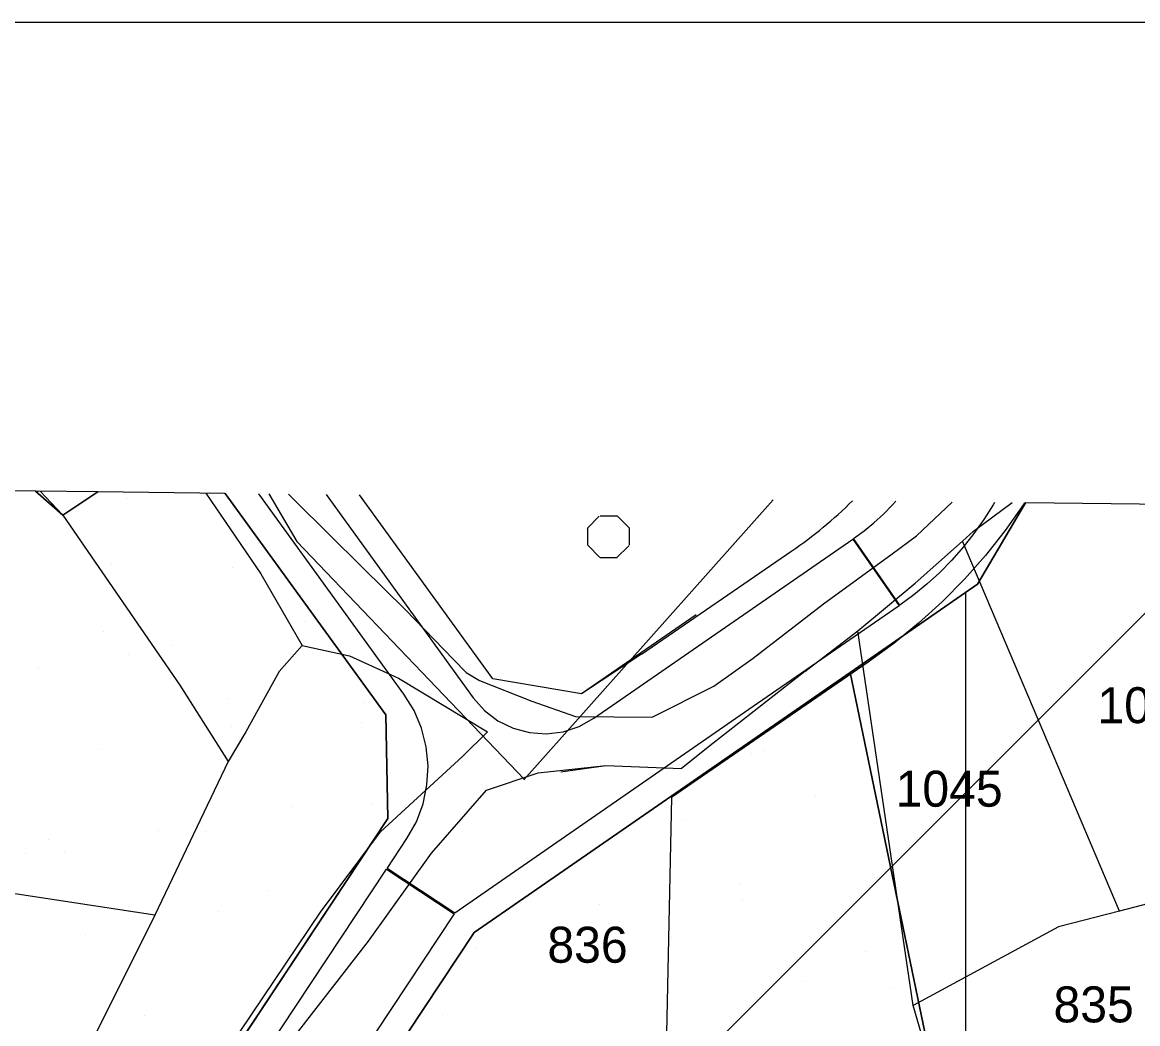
# Model space of a CAD drawing. Extents: x 410727 to 412947, y 4463506 to 4466382.
# Drawn here: x 410944.2 to 411068.2, y 4466270.3 to 4466381.6 of the extents above; entities that cross this region are included whole.
import ezdxf

# ---------------------------------------------------------------- set-up
doc = ezdxf.new("R2010")
doc.units = 0
for name, color, linetype in [('ADAKENARI', 7, 'Continuous'), ('F_ADAKENARI', 7, 'Continuous'), ('KALDIRIM', 7, 'Continuous'), ('KDS_PARSEL_NO', 7, 'Continuous'), ('KDS_PL', 7, 'Continuous'), ('LJ_ÇERÇEVE', 7, 'Continuous'), ('PL_AYA_PARK_DINLENME', 7, 'Continuous'), ('PL_KON_MEV_050', 7, 'Continuous'), ('SNR_KOYLER', 7, 'Continuous'), ('SNR_TR_AZGELISME', 7, 'Continuous'), ('TR_AZYOGUNLUK_MESKUN', 7, 'Continuous'), ('TR_OZELMAHSUL', 7, 'Continuous'), ('TR_PARKALANI', 7, 'Continuous'), ('Yerlesime_uygunluk_sınırı', 7, 'Continuous')]:
    doc.layers.add(name, color=color, linetype=linetype)

msp = doc.modelspace()

# ---------------------------------------------------------------- linework, layer by layer
at = {"layer": 'ADAKENARI'}
for p, q in [((410948.75, 4466326.83), (410945.69, 4466329.49)), ((410952.62, 4466329.41), (410948.75, 4466326.83)), ((410966.77, 4466329.24), (410984.62, 4466304.63)), ((411013.07, 4466311.39), (411029.75, 4466322.85)), ((411013.07, 4466311.39), (411029.75, 4466322.85)), ((411019.12, 4466315.76), (411006.4, 4466306.96)), ((411013.07, 4466311.39), (411006.4, 4466306.96)), ((411006.4, 4466306.96), (410996.54, 4466308.64)), ((410984.62, 4466304.63), (410984.87, 4466293.13)), ((410984.87, 4466293.13), (410937.01, 4466220.86))]:
    msp.add_line(p, q, dxfattribs=at)
for points in [[(411192.1, 4466326.6), (411199.04, 4466311.27), (411191.3, 4466278.41), (411195.67, 4466251.72), (411191.89, 4466226.13), (411190.31, 4466188.93), (411154.6, 4466192.84), (411154.89, 4466194.74), (411133.79, 4466195.19), (411131.16, 4466218.16), (411125.23, 4466237.12), (411061.36, 4466220.11), (411049.97, 4466245.63), (411049.01, 4466247.79), (411036.24, 4466309.36), (411050.41, 4466319.17), (411055.74, 4466328.2)], [(410994.47, 4466280.46), (411036.24, 4466309.36), (411049.01, 4466247.79), (411049.97, 4466245.63), (410970.35, 4466244.04), (410994.47, 4466280.46)]]:
    msp.add_lwpolyline(points, dxfattribs=at)
msp.add_arc((411001.42, 4466364.05), 50, 304.5085, 314.5543, dxfattribs=at)
msp.add_arc((411001.42, 4466364.05), 50, 304.5085, 314.5543, dxfattribs=at)
msp.add_arc((411001.42, 4466364.05), 50, 304.5085, 314.5543, dxfattribs=at)
at = {"layer": 'F_ADAKENARI'}
for p, q in [((410996.54, 4466308.64), (410981.72, 4466329.07)), ((411006.4, 4466306.96), (410996.54, 4466308.64))]:
    msp.add_line(p, q, dxfattribs=at)
at = {"layer": 'KALDIRIM'}
for points in [[(410977.99, 4466329.11), (410994.36, 4466306.54), (410995.6, 4466305.13), (410997.1, 4466303.99), (410998.78, 4466303.16), (411000.6, 4466302.66), (411002.47, 4466302.53), (411004.34, 4466302.76), (411006.12, 4466303.34), (411007.77, 4466304.25), (411020.83, 4466313.29), (411036.54, 4466324.17), (411041.67, 4466316.77), (411025.95, 4466305.89), (410992.29, 4466282.6), (410984.79, 4466287.57), (410986.99, 4466290.89), (410988.03, 4466292.76), (410988.78, 4466294.76), (410989.21, 4466296.85), (410989.33, 4466298.98), (410989.12, 4466301.1), (410988.6, 4466303.17), (410987.77, 4466305.13), (410986.65, 4466306.95), (410970.51, 4466329.2)], [(411052.28, 4466328.24), (411052.12, 4466327.98), (411052.12, 4466327.98), (411051.1, 4466326.35), (411050, 4466324.78), (411048.81, 4466323.28), (411047.54, 4466321.84), (411046.2, 4466320.47), (411044.78, 4466319.17), (411043.3, 4466317.96), (411041.75, 4466316.83), (411041.75, 4466316.83), (411036.63, 4466324.23), (411037.78, 4466325.07), (411038.89, 4466325.98), (411039.95, 4466326.95), (411040.95, 4466327.97), (411041.3, 4466328.37)], [(410877.26, 4466132.92), (410902.91, 4466163.94), (410984.73, 4466287.49), (410992.24, 4466282.52), (410910.15, 4466158.57), (410883.93, 4466126.86)]]:
    msp.add_lwpolyline(points, dxfattribs=at)
at = {"layer": 'KDS_PL'}
for p, q in [((410946.22, 4466329.48), (410948.75, 4466326.83)), ((410964.62, 4466329.27), (410970.75, 4466320.32)), ((410973.82, 4466329.16), (410974.53, 4466328.47)), ((410974.53, 4466328.47), (410982.05, 4466321)), ((411043.6, 4466324.53), (411047.58, 4466328.29)), ((411049.96, 4466325.05), (411054.26, 4466328.22)), ((410948.75, 4466326.83), (410961.76, 4466307.95)), ((411048.71, 4466323.94), (411049.96, 4466325.05)), ((411040.91, 4466322.53), (411043.6, 4466324.53)), ((411043.48, 4466319.28), (411048.71, 4466323.94)), ((411066.16, 4466282.83), (411048.71, 4466323.94)), ((411033.26, 4466316.96), (411040.91, 4466322.53)), ((410970.75, 4466320.32), (410975.33, 4466312.34)), ((410982.05, 4466321), (410986.83, 4466316.31)), ((411037.09, 4466313.99), (411043.48, 4466319.28)), ((410986.83, 4466316.31), (410992.16, 4466310.79)), ((411025.46, 4466310.93), (411033.26, 4466316.96)), ((411031.21, 4466309.44), (411037.09, 4466313.99)), ((411043.25, 4466272.34), (411037.09, 4466313.99)), ((410975.33, 4466312.34), (410972.78, 4466309.45)), ((410975.33, 4466312.34), (410980.6, 4466311.18)), ((410980.6, 4466311.18), (410986.04, 4466308.71)), ((410992.16, 4466310.79), (410993.55, 4466309.36)), ((411021.1, 4466307.83), (411025.46, 4466310.93)), ((410972.78, 4466309.45), (410969.07, 4466302.75)), ((410986.04, 4466308.71), (410995.93, 4466302.76)), ((410993.55, 4466309.36), (410995.04, 4466308.47)), ((411031.21, 4466309.44), (411020.98, 4466301.46)), ((410961.76, 4466307.95), (410967.11, 4466299.44)), ((410995.04, 4466308.47), (411000.88, 4466306.16)), ((411014.24, 4466304.39), (411021.1, 4466307.83)), ((411000.88, 4466306.16), (411005.7, 4466304.44)), ((411005.7, 4466304.44), (411014.24, 4466304.39)), ((410969.07, 4466302.75), (410967.11, 4466299.44)), ((410993.21, 4466300.04), (410995.93, 4466302.76)), ((411020.98, 4466301.46), (411017.49, 4466298.68)), ((410984.06, 4466291.62), (410993.21, 4466300.04)), ((410967.11, 4466299.44), (410958.96, 4466282.37)), ((411001.57, 4466298.18), (411009.07, 4466299)), ((411004.08, 4466298.31), (411009.07, 4466299)), ((411009.07, 4466299), (411017.49, 4466298.68)), ((410995.84, 4466296.27), (411001.57, 4466298.18)), ((410989.7, 4466289.26), (410995.84, 4466296.27)), ((410958.96, 4466282.37), (410894.78, 4466292.22)), ((410977.39, 4466282.71), (410984.06, 4466291.62)), ((410982.7, 4466279.49), (410989.7, 4466289.26)), ((411085.99, 4466287.93), (411066.16, 4466282.83)), ((410966.52, 4466266.61), (410977.39, 4466282.71)), ((411066.16, 4466282.83), (411059.38, 4466281.08)), ((410958.96, 4466282.37), (410947.29, 4466258.94)), ((411059.38, 4466281.08), (411043.25, 4466272.34)), ((410971.47, 4466265.05), (410982.7, 4466279.49)), ((411045.67, 4466264.11), (411043.25, 4466272.34))]:
    msp.add_line(p, q, dxfattribs=at)
at = {"layer": 'LJ_ÇERÇEVE'}
msp.add_lwpolyline([(410732.32, 4466381.6), (412946.74, 4466381.6), (412946.74, 4463506.16), (410732.32, 4463506.16)], close=True, dxfattribs=at)
at = {"layer": 'PL_AYA_PARK_DINLENME'}
for points in [[(410966.77, 4466329.24), (410952.62, 4466329.41), (410948.75, 4466326.83), (410945.69, 4466329.49), (410864.92, 4466330.44), (410865.03, 4466330.16), (410905.8, 4466318.77), (410931.26, 4466291.1), (410937.01, 4466220.86), (410984.87, 4466293.13), (410984.62, 4466304.63), (410966.77, 4466329.24)], [(410994.47, 4466280.46), (410970.35, 4466244.04), (411049.97, 4466245.63), (411049.01, 4466247.79), (411036.24, 4466309.36), (410994.47, 4466280.46)]]:
    msp.add_lwpolyline(points, dxfattribs=at)
at = {"layer": 'PL_KON_MEV_050'}
for points in [[(410952.62, 4466329.41), (410945.69, 4466329.49), (410948.75, 4466326.83), (410952.62, 4466329.41)], [(411192.1, 4466326.6), (411055.74, 4466328.2), (411050.41, 4466319.17), (411036.24, 4466309.36), (411049.01, 4466247.79), (411049.97, 4466245.63), (411058.74, 4466226), (411061.36, 4466220.11), (411125.23, 4466237.12), (411131.16, 4466218.16), (411133.79, 4466195.19), (411154.89, 4466194.74), (411154.6, 4466192.84), (411190.31, 4466188.93), (411191.89, 4466226.13), (411195.67, 4466251.72), (411191.3, 4466278.41), (411199.04, 4466311.27), (411192.1, 4466326.6)]]:
    msp.add_lwpolyline(points, dxfattribs=at)
at = {"layer": 'SNR_KOYLER'}
for p, q in [((411055.52, 4466328.03), (411053.48, 4466325.14)), ((411055.63, 4466328.2), (411055.52, 4466328.03)), ((411053.48, 4466325.14), (411051.29, 4466322.36)), ((411051.29, 4466322.36), (411048.95, 4466319.71)), ((411048.95, 4466319.71), (411046.46, 4466317.19)), ((411046.46, 4466317.19), (411043.85, 4466314.81)), ((411043.85, 4466314.81), (411041.1, 4466312.57)), ((411041.1, 4466312.57), (411038.24, 4466310.49)), ((411038.24, 4466310.49), (411016.4, 4466295.47)), ((411016.4, 4466295.47), (411011.82, 4466089.82))]:
    msp.add_line(p, q, dxfattribs=at)
at = {"layer": 'SNR_TR_AZGELISME'}
msp.add_line((411015.66, 4466262.59), (411080.98, 4466327.9), dxfattribs=at)
at = {"layer": 'TR_AZYOGUNLUK_MESKUN'}
for p, q in [((410945.91, 4466329.3), (410945.91, 4466329.49)), ((411049.1, 4466247.57), (411049.1, 4466318.27))]:
    msp.add_line(p, q, dxfattribs=at)
msp.add_lwpolyline([(411055.74, 4466328.2), (411050.41, 4466319.17), (411036.24, 4466309.36), (411049.01, 4466247.79), (411049.97, 4466245.63), (411058.74, 4466226), (411061.36, 4466220.11), (411125.23, 4466237.12), (411131.16, 4466218.16), (411133.79, 4466195.19), (411154.89, 4466194.74), (411154.6, 4466192.84), (411190.31, 4466188.93), (411191.89, 4466226.13), (411195.67, 4466251.72), (411191.3, 4466278.41), (411199.04, 4466311.27), (411192.1, 4466326.6)], dxfattribs=at)
at = {"layer": 'TR_OZELMAHSUL'}
for p, q in [((411007.01, 4466325.35), (411008.36, 4466326.7)), ((411008.44, 4466326.76), (411010.36, 4466326.76)), ((411011.7, 4466325.4), (411010.34, 4466326.75)), ((411007.09, 4466323.49), (411007.09, 4466325.41)), ((411011.71, 4466323.49), (411011.71, 4466325.41)), ((411008.43, 4466322.13), (411007.07, 4466323.48)), ((411010.28, 4466322.08), (411011.63, 4466323.43)), ((411008.44, 4466322.14), (411010.36, 4466322.14))]:
    msp.add_line(p, q, dxfattribs=at)
at = {"layer": 'TR_PARKALANI'}
for p, q in [((410955.9, 4466328.71), (410955.9, 4466328.71)), ((410955.9, 4466328.71), (410955.9, 4466328.71)), ((410955.9, 4466328.71), (410955.9, 4466328.71)), ((410968.89, 4466323.96), (410968.89, 4466323.96)), ((410968.89, 4466323.96), (410968.89, 4466323.96)), ((410968.89, 4466323.96), (410968.89, 4466323.96)), ((410968.89, 4466323.96), (410968.89, 4466323.96)), ((410968.89, 4466323.96), (410968.89, 4466323.96)), ((410968.89, 4466323.96), (410968.89, 4466323.96)), ((410954.12, 4466321.35), (410954.12, 4466321.35)), ((410954.12, 4466321.35), (410954.12, 4466321.35)), ((410954.12, 4466321.35), (410954.12, 4466321.35)), ((410954.12, 4466321.35), (410954.12, 4466321.35)), ((410954.12, 4466321.35), (410954.12, 4466321.35)), ((410954.12, 4466321.35), (410954.12, 4466321.35)), ((410967.55, 4466320.98), (410967.55, 4466320.98)), ((410967.55, 4466320.98), (410967.55, 4466320.98)), ((410967.55, 4466320.98), (410967.55, 4466320.98)), ((410975.55, 4466314.98), (410975.55, 4466314.98)), ((410975.55, 4466314.98), (410975.55, 4466314.98)), ((410975.55, 4466314.98), (410975.55, 4466314.98)), ((410975.55, 4466314.98), (410975.55, 4466314.98)), ((410975.55, 4466314.98), (410975.55, 4466314.98)), ((410975.55, 4466314.98), (410975.55, 4466314.98)), ((410953.3, 4466313.94), (410953.3, 4466313.94)), ((410953.3, 4466313.94), (410953.3, 4466313.94)), ((410953.3, 4466313.94), (410953.3, 4466313.94)), ((410960.78, 4466312.37), (410960.78, 4466312.37)), ((410960.78, 4466312.37), (410960.78, 4466312.37)), ((410960.78, 4466312.37), (410960.78, 4466312.37)), ((410960.78, 4466312.37), (410960.78, 4466312.37)), ((410960.78, 4466312.37), (410960.78, 4466312.37)), ((410960.78, 4466312.37), (410960.78, 4466312.37)), ((410956.06, 4466311.34), (410956.06, 4466311.34)), ((410956.06, 4466311.34), (410956.06, 4466311.34)), ((410956.06, 4466311.34), (410956.06, 4466311.34)), ((410956.06, 4466311.34), (410956.06, 4466311.34)), ((410956.06, 4466311.34), (410956.06, 4466311.34)), ((410956.06, 4466311.34), (410956.06, 4466311.34)), ((410946, 4466309.77), (410946, 4466309.77)), ((410946, 4466309.77), (410946, 4466309.77)), ((410946, 4466309.77), (410946, 4466309.77)), ((410946, 4466309.77), (410946, 4466309.77)), ((410946, 4466309.77), (410946, 4466309.77)), ((410946, 4466309.77), (410946, 4466309.77)), ((410967.2, 4466306.41), (410967.2, 4466306.41)), ((410967.2, 4466306.41), (410967.2, 4466306.41)), ((410967.2, 4466306.41), (410967.2, 4466306.41)), ((410982.21, 4466306), (410982.21, 4466306)), ((410982.21, 4466306), (410982.21, 4466306)), ((410982.21, 4466306), (410982.21, 4466306)), ((410982.21, 4466306), (410982.21, 4466306)), ((410982.21, 4466306), (410982.21, 4466306)), ((410982.21, 4466306), (410982.21, 4466306)), ((410981.98, 4466303.81), (410981.98, 4466303.81)), ((410981.98, 4466303.81), (410981.98, 4466303.81)), ((410981.98, 4466303.81), (410981.98, 4466303.81)), ((410967.44, 4466303.39), (410967.44, 4466303.39)), ((410967.44, 4466303.39), (410967.44, 4466303.39)), ((410967.44, 4466303.39), (410967.44, 4466303.39)), ((410967.44, 4466303.39), (410967.44, 4466303.39)), ((410967.44, 4466303.39), (410967.44, 4466303.39)), ((410967.44, 4466303.39), (410967.44, 4466303.39)), ((410952.67, 4466300.79), (410952.67, 4466300.79)), ((410952.67, 4466300.79), (410952.67, 4466300.79)), ((410952.67, 4466300.79), (410952.67, 4466300.79)), ((410952.67, 4466300.79), (410952.67, 4466300.79)), ((410952.67, 4466300.79), (410952.67, 4466300.79)), ((410952.67, 4466300.79), (410952.67, 4466300.79)), ((411025.28, 4466300.39), (411025.28, 4466300.39)), ((411025.28, 4466300.39), (411025.28, 4466300.39)), ((411026.61, 4466300.62), (411026.61, 4466300.62)), ((411032.34, 4466295.58), (411032.34, 4466295.58)), ((411032.34, 4466295.58), (411032.34, 4466295.58)), ((410974.1, 4466294.41), (410974.1, 4466294.41)), ((410974.1, 4466294.41), (410974.1, 4466294.41)), ((410974.1, 4466294.41), (410974.1, 4466294.41)), ((410974.1, 4466294.41), (410974.1, 4466294.41)), ((410974.1, 4466294.41), (410974.1, 4466294.41)), ((410974.1, 4466294.41), (410974.1, 4466294.41)), ((410983, 4466294.78), (410983, 4466294.78)), ((410983, 4466294.78), (410983, 4466294.78)), ((410983, 4466294.78), (410983, 4466294.78)), ((411017.57, 4466292.98), (411017.57, 4466292.98)), ((411017.57, 4466292.98), (411017.57, 4466292.98)), ((410959.33, 4466291.81), (410959.33, 4466291.81)), ((410959.33, 4466291.81), (410959.33, 4466291.81)), ((410959.33, 4466291.81), (410959.33, 4466291.81)), ((410959.33, 4466291.81), (410959.33, 4466291.81)), ((410959.33, 4466291.81), (410959.33, 4466291.81)), ((410959.33, 4466291.81), (410959.33, 4466291.81)), ((410964.6, 4466291.64), (410964.6, 4466291.64)), ((410964.6, 4466291.64), (410964.6, 4466291.64)), ((410964.6, 4466291.64), (410964.6, 4466291.64)), ((410947.17, 4466290.82), (410947.17, 4466290.82)), ((410947.17, 4466290.82), (410947.17, 4466290.82)), ((410947.17, 4466290.82), (410947.17, 4466290.82)), ((410944.55, 4466289.2), (410944.55, 4466289.2)), ((410944.55, 4466289.2), (410944.55, 4466289.2)), ((410944.55, 4466289.2), (410944.55, 4466289.2)), ((410944.55, 4466289.2), (410944.55, 4466289.2)), ((410944.55, 4466289.2), (410944.55, 4466289.2)), ((410944.55, 4466289.2), (410944.55, 4466289.2)), ((410948.96, 4466289.32), (410948.96, 4466289.32)), ((410948.96, 4466289.32), (410948.96, 4466289.32)), ((410948.96, 4466289.32), (410948.96, 4466289.32)), ((411039, 4466286.6), (411039, 4466286.6)), ((411039, 4466286.6), (411039, 4466286.6)), ((410971.51, 4466285.14), (410971.51, 4466285.14)), ((410971.51, 4466285.14), (410971.51, 4466285.14)), ((410971.51, 4466285.14), (410971.51, 4466285.14)), ((410971.51, 4466285.14), (410971.51, 4466285.14)), ((410971.51, 4466285.14), (410971.51, 4466285.14)), ((410971.51, 4466285.14), (410971.51, 4466285.14)), ((411024.01, 4466285.84), (411024.01, 4466285.84)), ((410978.5, 4466284.11), (410978.5, 4466284.11)), ((410978.5, 4466284.11), (410978.5, 4466284.11)), ((410978.5, 4466284.11), (410978.5, 4466284.11)), ((411024.23, 4466284), (411024.23, 4466284)), ((411024.23, 4466284), (411024.23, 4466284)), ((410965.99, 4466282.83), (410965.99, 4466282.83)), ((410965.99, 4466282.83), (410965.99, 4466282.83)), ((410965.99, 4466282.83), (410965.99, 4466282.83)), ((410965.99, 4466282.83), (410965.99, 4466282.83)), ((410965.99, 4466282.83), (410965.99, 4466282.83)), ((410965.99, 4466282.83), (410965.99, 4466282.83)), ((411008.37, 4466283.52), (411008.37, 4466283.52)), ((411009.46, 4466281.4), (411009.46, 4466281.4)), ((411009.46, 4466281.4), (411009.46, 4466281.4)), ((410951.21, 4466280.22), (410951.21, 4466280.22)), ((410951.21, 4466280.22), (410951.21, 4466280.22)), ((410951.21, 4466280.22), (410951.21, 4466280.22)), ((410951.21, 4466280.22), (410951.21, 4466280.22)), ((410951.21, 4466280.22), (410951.21, 4466280.22)), ((410951.21, 4466280.22), (410951.21, 4466280.22)), ((411016.39, 4466279.87), (411016.39, 4466279.87)), ((410994.68, 4466278.79), (410994.68, 4466278.79)), ((410994.68, 4466278.79), (410994.68, 4466278.79)), ((411037.91, 4466278.31), (411037.91, 4466278.31)), ((411030.89, 4466275.02), (411030.89, 4466275.02)), ((411030.89, 4466275.02), (411030.89, 4466275.02)), ((411040.73, 4466274.2), (411040.73, 4466274.2)), ((411040.73, 4466274.2), (411040.73, 4466274.2)), ((411016.12, 4466272.42), (411016.12, 4466272.42)), ((411016.12, 4466272.42), (411016.12, 4466272.42)), ((410957.87, 4466271.25), (410957.87, 4466271.25)), ((410957.87, 4466271.25), (410957.87, 4466271.25)), ((410957.87, 4466271.25), (410957.87, 4466271.25)), ((410957.87, 4466271.25), (410957.87, 4466271.25)), ((410957.87, 4466271.25), (410957.87, 4466271.25)), ((410957.87, 4466271.25), (410957.87, 4466271.25)), ((410990.99, 4466271.36), (410990.99, 4466271.36))]:
    msp.add_line(p, q, dxfattribs=at)
at = {"layer": 'Yerlesime_uygunluk_sınırı'}
for points in [[(410971.62, 4466329.19), (410974.73, 4466323.92), (411000.04, 4466297.46)], [(411027.7, 4466328.53), (410999.98, 4466297.4), (411027.7, 4466328.53)]]:
    msp.add_lwpolyline(points, dxfattribs=at)

# ---------------------------------------------------------------- texts
at = {"layer": 'KDS_PARSEL_NO'}
for s, p in [('1046', (411063.72, 4466303.71)), ('1045', (411041.29, 4466294.43)), ('836', (411002.59, 4466277.09)), ('835', (411058.84, 4466270.46))]:
    msp.add_text(s, height=4, dxfattribs=at).set_placement(p)

doc.saveas('drawing.dxf')
